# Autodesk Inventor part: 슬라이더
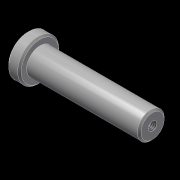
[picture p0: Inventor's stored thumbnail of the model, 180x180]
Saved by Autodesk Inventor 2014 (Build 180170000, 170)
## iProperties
Company: 한국ATC센터
Created: 2014-08
Part Number: 슬라이더
Document SubType Name: Modeling
Designer: KYOUNG IL JANG
Density: 7.86 g/cm^3
Material: 강철, 연강
Appearance: 강철
Mass: 107.623 g
Surface Area: 43.9337 cm^2
Volume: 13.6925 cm^3
Author: KYOUNG IL JANG
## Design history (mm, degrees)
sketch "스케치1"
  geometry: L1 (-7, 0)-(63, 0); L2 (63, 0)-(63, 7.5); L3 (63, 7.5)-(0, 7.5); L4 (-7, 0)-(-7, 11.5); L5 (-7, 11.5)-(0, 11.5); L6 (0, 11.5)-(0, 7.5); 1 further point
  constraints: 12 end point, 3 perpendicular, 2 horizontal, 2 point on line, 1 parallel
  dimensions: "d1" = 70 distance of L1.start L1.end; "d19" = 15 diameter of L3 L1; "d20" = 7 distance of L4.end L5.end; "d21" = 23 diameter of L5 L1
revolve "회전1" stored, may be unused: angle "d4" = 90 deg
chamfer "모따기1" distance "d16" = 1; stored, may be unused: second distance "d17" = 2, angle "d18" = 45 deg
hole "구멍2" diameter "d24" = 4.917; stored, may be unused: countersink angle "d28" = 90 deg, drill point angle "d30" = 118 deg; dims "d22" = 10, "d23" = 10, "d25" = 10, "d26" = 4, "d27" = 2, "d29" = 13
node "솔리드1"
